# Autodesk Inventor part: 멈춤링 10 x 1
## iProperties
IsCustomPart: 0
Company: 한국ATC센터
Created: 2014-07
Part Number: 멈춤링 10 x 1
Material: Steel, Mild
Description: 리테이닝 링(C형)
Document SubType Name: Modeling
Standard: KS B 1336
Designer: KYOUNG IL JANG
Standards Organization: KS
Language: ko-KR
Size Designation: 10 x 1
Categories: <MemberInstance><Categories><Category DisplayName="샤프트 부품" InternalName="7f7aeb1f-a693-4053-b835-cee3144e0d98" Mnemonic="SHFT"><Category DisplayName="써클립" Inter
Density: 1 g/cm^3
Author: KYOUNG IL JANG
